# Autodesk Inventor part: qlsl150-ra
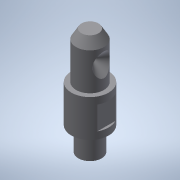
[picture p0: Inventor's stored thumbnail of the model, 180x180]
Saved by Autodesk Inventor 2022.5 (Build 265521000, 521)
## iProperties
Created: 2016-12
Part Number: qlsl150-ra
Material: 一般
Document SubType Name: Modeling
Designer: imaocorp
Density: 1 g/cm^3
Appearance: 既定
Author: imaocorp
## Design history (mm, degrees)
node "qlsl150-ra.x_t1"
node "qlsl150-ra"
node "Base1"
